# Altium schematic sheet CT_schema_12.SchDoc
size 389 x 385 mm
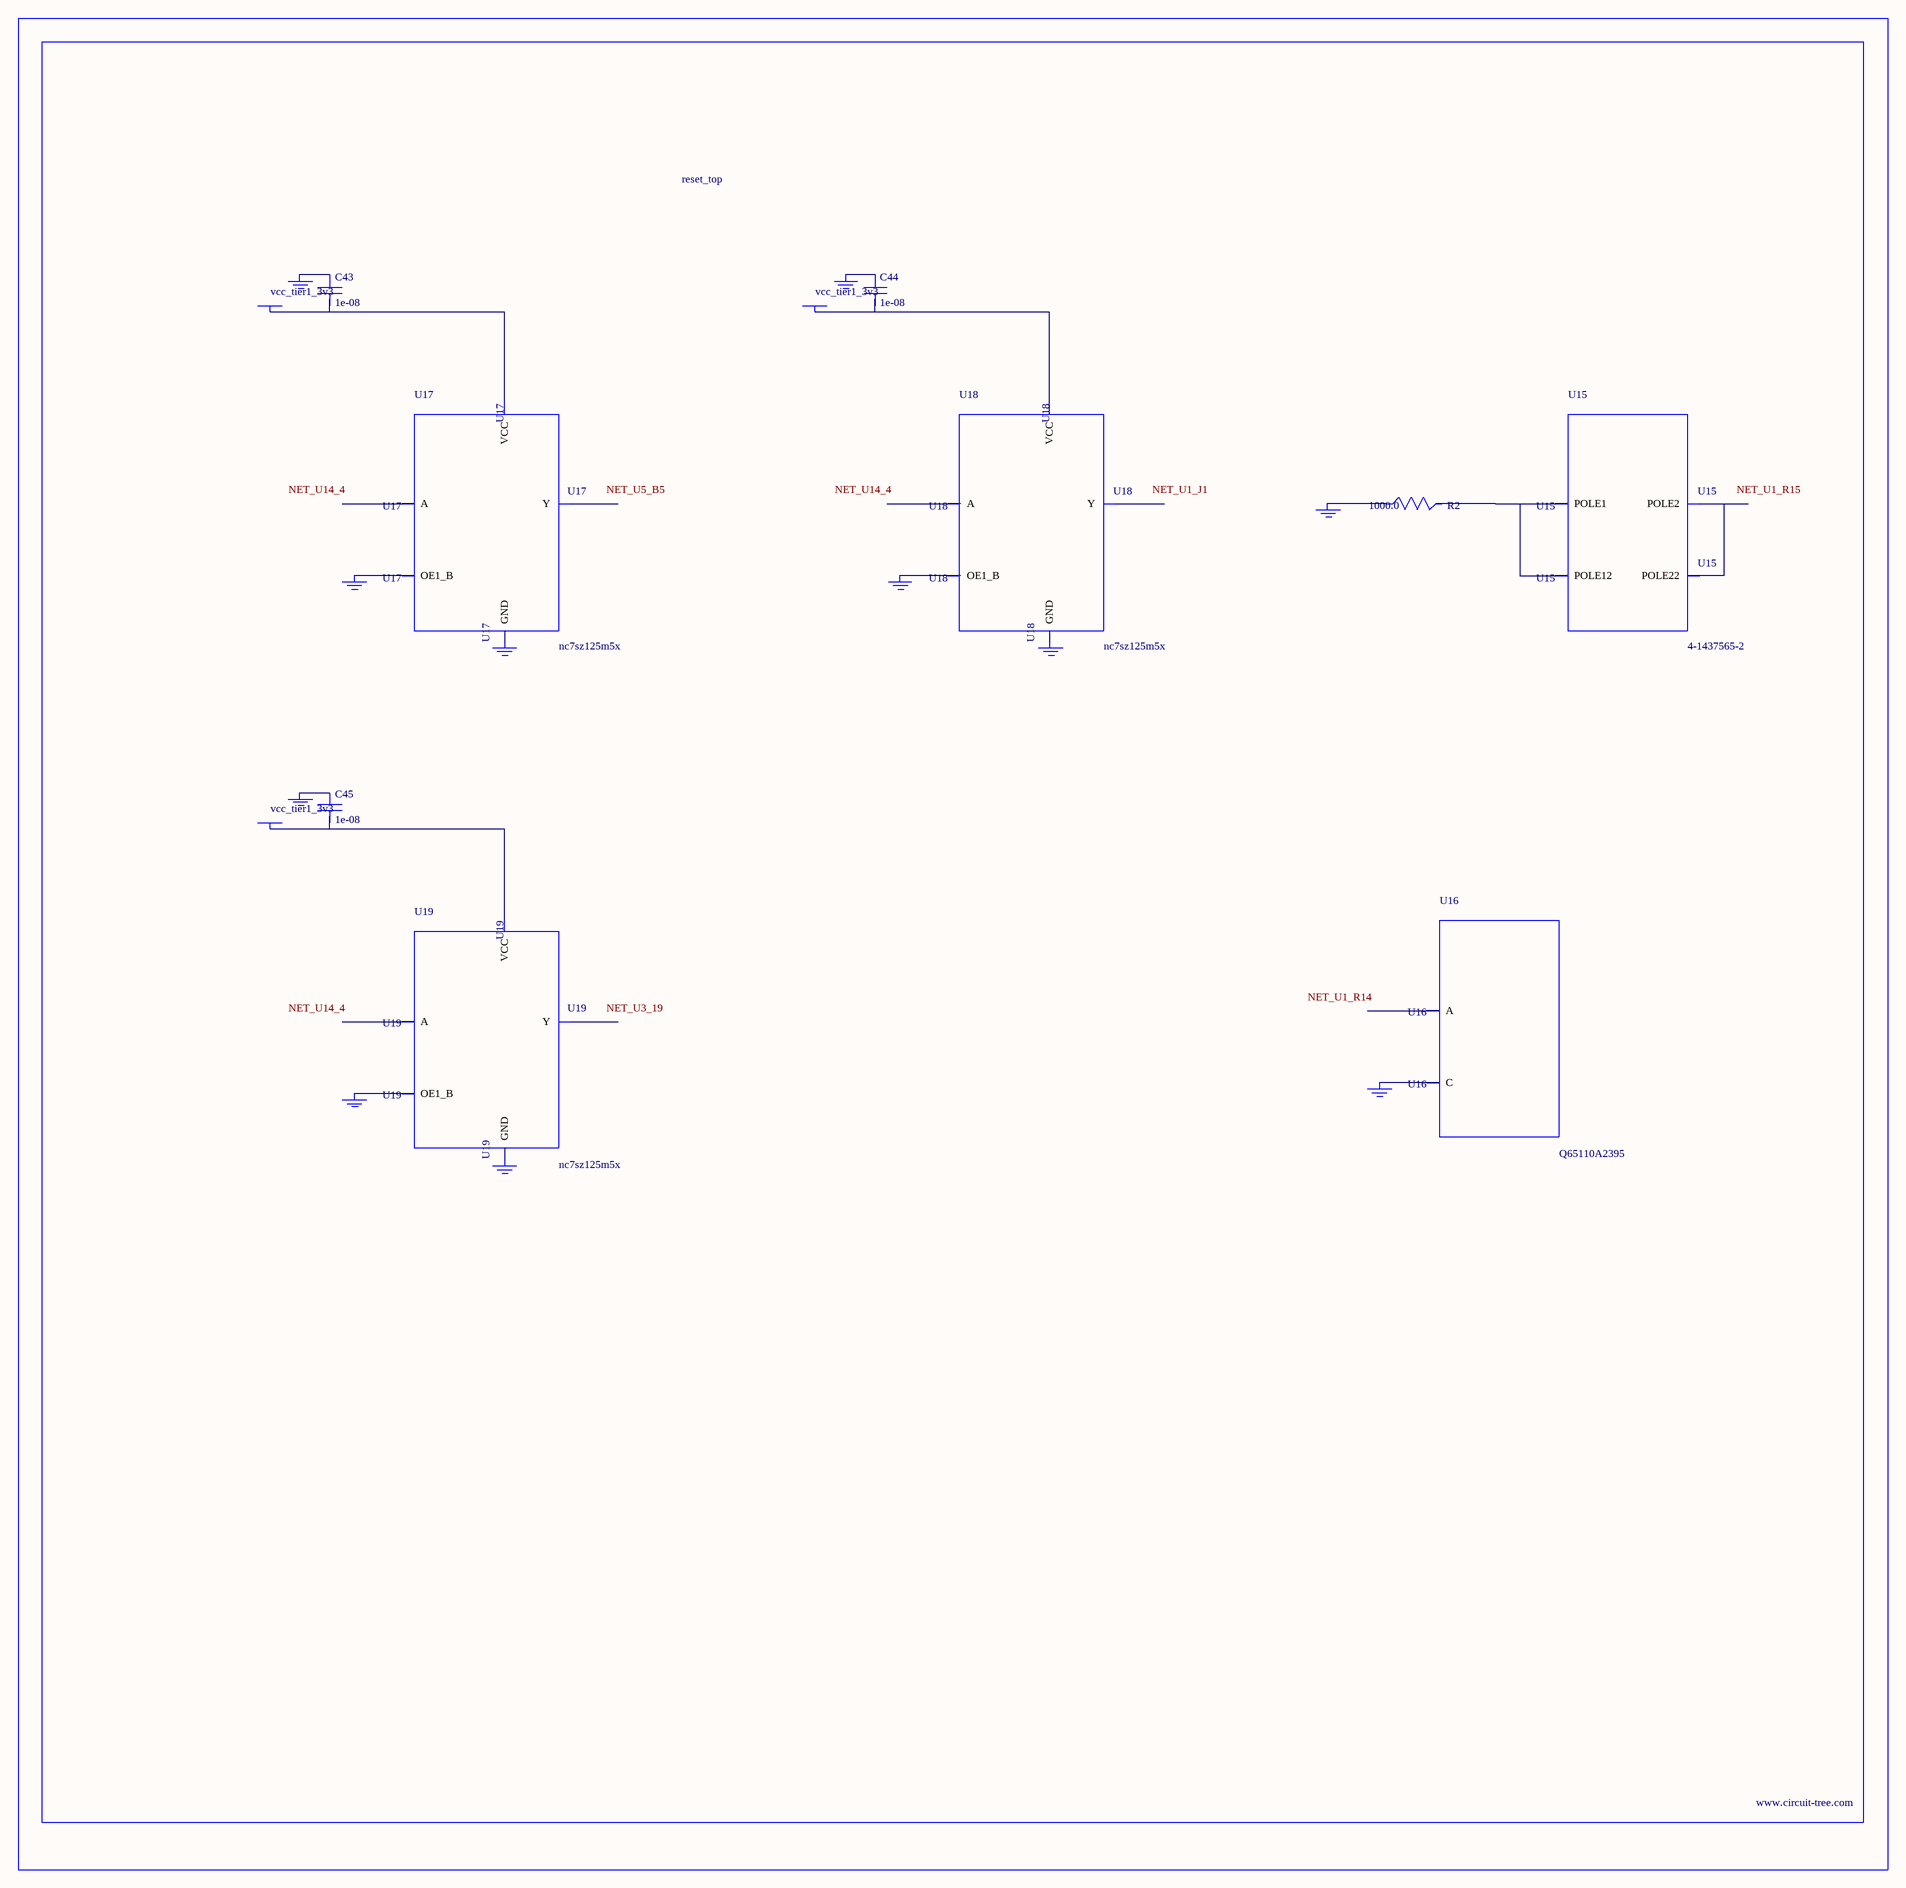
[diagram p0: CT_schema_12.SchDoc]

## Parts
BORDER11  (no value)
C43  1e-08  [C0402]
C44  1e-08  [C0402]
C45  1e-08  [C0402]
GND_INSTANCE_11_0  (no value)
GND_INSTANCE_11_1  (no value)
GND_INSTANCE_11_2  (no value)
GND_INSTANCE_11_3  (no value)
GND_INSTANCE_11_4  (no value)
GND_INSTANCE_11_5  (no value)
GND_INSTANCE_11_6  (no value)
GND_INSTANCE_11_7  (no value)
GND_INSTANCE_11_8  (no value)
GND_INSTANCE_11_9  (no value)
GND_INSTANCE_11_10  (no value)
POWER_INSTANCE_11_0  vcc_tier1_3v3
POWER_INSTANCE_11_1  vcc_tier1_3v3
POWER_INSTANCE_11_2  vcc_tier1_3v3
R2  1000.0  [R0603]
U15  4-1437565-2  [SW_4-1437565-2]
U16  Q65110A2395  [LGM67K-G1J2-24-Z]
U17  nc7sz125m5x  [NC7SZ125M5X]
U18  nc7sz125m5x  [NC7SZ125M5X]
U19  nc7sz125m5x  [NC7SZ125M5X]

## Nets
NetC43_1: C43.1 GND_INSTANCE_11_2.0(GND)
NetC43_2: C43.2 POWER_INSTANCE_11_0.0(PWR) U17.5(VCC)
NetC44_1: C44.1 GND_INSTANCE_11_5.0(GND)
NetC44_2: C44.2 POWER_INSTANCE_11_1.0(PWR) U18.5(VCC)
NetC45_1: C45.1 GND_INSTANCE_11_8.0(GND)
NetC45_2: C45.2 POWER_INSTANCE_11_2.0(PWR) U19.5(VCC)
NetGND_INSTANCE_11_0_0: GND_INSTANCE_11_0.0(GND) R2.1
NetGND_INSTANCE_11_1_0: GND_INSTANCE_11_1.0(GND) U16.C
NetGND_INSTANCE_11_3_0: GND_INSTANCE_11_3.0(GND) U17.1(OE1_B)
NetGND_INSTANCE_11_4_0: GND_INSTANCE_11_4.0(GND) U17.3(GND)
NetGND_INSTANCE_11_6_0: GND_INSTANCE_11_6.0(GND) U18.1(OE1_B)
NetGND_INSTANCE_11_7_0: GND_INSTANCE_11_7.0(GND) U18.3(GND)
NetGND_INSTANCE_11_9_0: GND_INSTANCE_11_9.0(GND) U19.1(OE1_B)
NetGND_INSTANCE_11_10_0: GND_INSTANCE_11_10.0(GND) U19.3(GND)
NetR2_2: R2.2 U15.1(POLE1) U15.2(POLE12)
NetU15_3: U15.3(POLE2) U15.4(POLE22)

Not connected (* = marked no-connect by the designer): U16 A; U17 2(A) 4(Y); U18 2(A) 4(Y); U19 2(A) 4(Y)

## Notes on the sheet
- Labels drawn without touching a wire or pin: NET_U1_J1, NET_U1_R14, NET_U1_R15, NET_U3_19, NET_U5_B5, NET_U14_4

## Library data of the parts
BORDER11 = BORDER_PAGE11
C43-C45 = C0402C103K3RAC
GND_INSTANCE_11_0-GND_INSTANCE_11_10 = GND
POWER_INSTANCE_11_0-POWER_INSTANCE_11_2 = PWR
R2 = RC0603JR-071KL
